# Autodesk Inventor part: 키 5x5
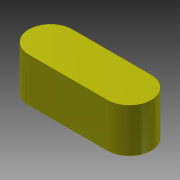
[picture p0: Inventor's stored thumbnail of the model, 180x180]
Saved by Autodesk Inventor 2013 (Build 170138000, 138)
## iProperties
Created: 2016-04
Part Number: 키 5x5
Document SubType Name: Modeling
Designer: mdu
Density: 7.86 g/cm^3
Mass: 2.54015 g
Surface Area: 2.9781 cm^2
Volume: 0.323175 cm^3
Material: 강철, 연강
Author: mdu
Revision Number: 1
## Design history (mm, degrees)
sketch "스케치1"
  geometry: L1 (-4.5, -2.5)-(4.5, -2.5); L2 (4.5, 2.5)-(-4.5, 2.5); A1 r 2.5 centre (4.5, 0) between (4.5, -2.5) and (4.5, 2.5); A2 r 2.5 centre (-4.5, 0) between (-4.5, 2.5) and (-4.5, -2.5); 2 further points
  constraints: 4 end point, 4 point on circle, 4 tangent, 2 centre point, 1 horizontal, 1 horizontal alignment, 1 midpoint, 1 parallel, 1 vertical alignment
  dimensions: "d0" = 5 distance between parallel lines of L1 L2; "d1" = 14 dimension on A1 A2
extrude "돌출1" new body sketch "스케치1" stored distance "d2" = 5; taper "d3" = 0 deg
chamfer "모따기1" distance "d4" = 0.5; stored, may be unused: second distance "d5" = 2, angle "d6" = 45 deg
node "솔리드1"
other parameters: "d0" = 5
